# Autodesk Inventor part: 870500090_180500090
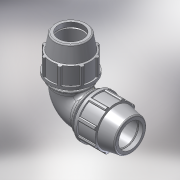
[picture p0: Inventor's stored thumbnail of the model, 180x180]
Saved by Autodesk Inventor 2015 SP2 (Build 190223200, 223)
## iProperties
Created: 2017-02
Part Number: 870500090_180500090
Material: PVC-Piping
Description: PLASSON 90° ELBOW 90-90
Document SubType Name: Modeling
Designer: KIM
Mass: 92.6774 g
Surface Area: 199.44 cm^2
Volume: 66.1981 cm^3
Density: 1.4 g/cm^3
Appearance: Smooth - White
Author: KIM
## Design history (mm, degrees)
derived "87050.ipt"
feature "Solid1::87050.ipt"
tag "TaggingFeature1"
body "Solid1"
other parameters: "d4" = 18, "d5" = 54, "d7" = 152, "d9" = 30.85714, "d11" = 7.2, "d13" = 120 deg, "d14" = 117, "d15" = 10 deg, "d16" = 132.24, "d18" = 4.5, "d19" = 35 deg, "d20" = 17.5 deg, "d21" = 141.36, "d23" = 0, "d25" = 360 deg, "d27" = 3.04, "d33" = 1.8, "d42" = 73.44, "d43" = 4.56, "d46" = 2.7, "d51" = 216, "d59" = 90 deg, "d63" = 161, "d64" = 81, "d67" = 114, "d68" = 12.96, "d70" = 90 deg, "d71" = 13.5, "d72" = 10.13333, "d73" = 0, "d75" = 90 deg, "d77" = 129.5952, "d78" = 4.32, "E_" = 152, "A_" = 216, "l_" = 161
